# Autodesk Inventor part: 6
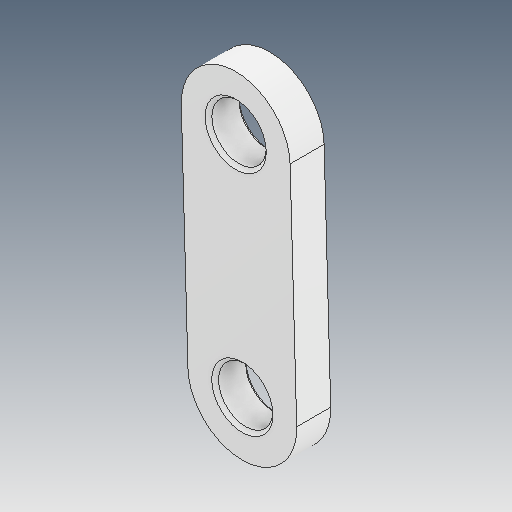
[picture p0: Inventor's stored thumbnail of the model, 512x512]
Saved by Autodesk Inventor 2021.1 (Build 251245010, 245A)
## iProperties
Created: 2021-06
Part Number: 6
Material: Ogólny
Document SubType Name: Modeling
Designer: user
Density: 1 g/cm^3
Appearance: Domyślna
Author: user
Revision Number: ÈÎºÎ
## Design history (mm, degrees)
feature "ÊäÈë1"
node "Bryła1"
